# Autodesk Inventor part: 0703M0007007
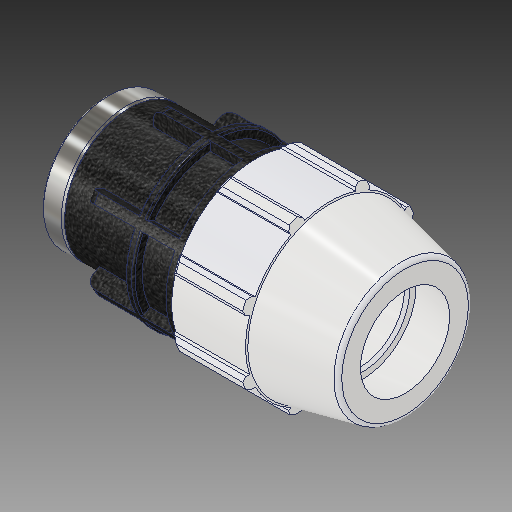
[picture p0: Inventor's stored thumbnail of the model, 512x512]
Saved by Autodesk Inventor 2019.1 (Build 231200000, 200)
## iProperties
Created: 2017-02
Part Number: 0703M0007007
Material: PVC-Piping
Description: PLASSON FEMALE ADAPTOR 3/4'' - 3/4''F
Document SubType Name: Modeling
Designer: KIM
Mass: 92.6774 g
Surface Area: 199.44 cm^2
Volume: 66.1981 cm^3
Density: 1.4 g/cm^3
Appearance: PTFE
Author: KIM
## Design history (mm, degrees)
derived "0703M0.ipt"
feature "Solid1::0703M0.ipt"
tag "TaggingFeature1"
body "Solid1"
other parameters: "d2" = 26.6, "d4" = 12.7, "d5" = 22.225, "d7" = 54.102, "d9" = 12.7, "d11" = 2.54, "d12" = 43.2816, "d13" = 120 deg, "d14" = 39.9, "d15" = 12 deg, "d16" = 48.6918, "d18" = 1.33, "d19" = 35 deg, "d20" = 17.5 deg, "d21" = 50.31486, "d23" = 0, "d25" = 360 deg, "d27" = 1.08204, "d34" = 2.7051, "d35" = 26.67, "d36" = 0, "d42" = 22.225, "d43" = 1.62306, "d46" = 0.798, "d49" = 64.008, "d51" = 88.9, "d53" = 0.532, "d55" = 360 deg, "d61" = 21.082, "d62" = 21.28, "d63" = 24.117, "d64" = 29.63333, "d65" = 2.7051, "d66" = 0.5, "d67" = 1, "d68" = 6.3246, "d69" = 38.95344, "d70" = 1.35255, "d_" = 26.6, "E_" = 54.102, "H_" = 88.9, "l_" = 64.008, "l_2" = 21.082, "Rp_" = 24.117
